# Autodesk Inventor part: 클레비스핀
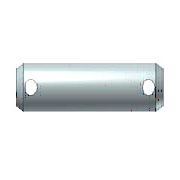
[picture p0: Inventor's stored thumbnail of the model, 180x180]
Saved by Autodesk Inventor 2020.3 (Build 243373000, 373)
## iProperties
Created: 2012-02
Part Number: 클레비스핀
Material: 강철
Description: 머리가 없는 클레비스 핀 B
Document SubType Name: Modeling
Standard: ISO 2340
Designer: mduedu
Standard Revision: Second edition 1986-11-01
Standards Organization: ISO
Language: ko-KR
Size Designation: B - 8 x 45
Categories: <MemberInstance><Categories><Category DisplayName="조임쇠" InternalName="e4da775c-781d-43d5-af7c-5136215cf5a6" Mnemonic="FSTN"><Category DisplayName="핀" InternalNa
Density: 7.85 g/cm^3
Appearance: 반광택
IsCustomPart: 1
Author: mduedu
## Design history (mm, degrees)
sketch "스케치1"
  geometry: L1 (-4.5, 0)-(-4.5, 4); L2 (-4.5, 4)-(35.5, 4); L3 (35.5, 4)-(35.5, 0); L4 (-4.5, 0)-(35.5, 0); L5 (0, -2)-(0, 5) reference; L6 (-13.5, 0)-(49.5, 0) reference; C1 r 1 at (-1, 0); C2 r 1 at (32, 0)
  constraints: 8 end point, 2 centre point, 2 perpendicular, 2 point on line, 1 collinear, 1 parallel, 1 tangent, 1 vertical
  dimensions: "d0" = 8 diameter of L2 L4 (= NND); "d1" = 40 distance of L1.end L2.end (= NLG); "d2" = 3.5 distance from line of L1 C1.centre (= DIST1); "d3" = 3.5 distance from line of L3 C2.centre (= DIST2); "d4" = 2 diameter of C1 (= BOR1); "d5" = 2 diameter of C2 (= BOR2)
revolve "본체" stored, may be unused: angle "d7" = 90 deg
extrude "구멍1" cut sketch "스케치1" extent not by distance; taper "d6" = 0 deg; stored distance "d8" = 10
extrude "구멍2" cut sketch "스케치1" extent not by distance; taper "d13" = 0 deg; stored distance "d14" = 10
workaxis "Work Axis1"
workaxis "Work Axis2"
workplane "Work Plane1"
node "작업 평면5"
body "Solid1"
chamfer "모따기2" distance "d9" = 2 (= PHH2); stored, may be unused: angle "d10" = 30 deg (= FAWI2), second distance "d40" = 2 (= PHH2)
chamfer "모따기1" distance "d11" = 2 (= PHH1); stored, may be unused: angle "d12" = 30 deg (= FAWI1), second distance "d41" = 2 (= PHH1)
other parameters: "NLG" = 40 [user parameter; used in 1 equation term], "NND" = 8 [user parameter; used in 1 equation term], "PHH1" = 2 [user parameter; used in 3 equation terms], "PHH2" = 2 (= PHH1) [user parameter; used in 2 equation terms], "FAWI1" = 30 deg [user parameter; used in 1 equation term], "FAWI2" = 30 deg [user parameter; used in 1 equation term], "DIST1" = 3.5 [user parameter; used in 4 equation terms], "DIST2" = 3.5 (= DIST1) [user parameter; used in 1 equation term], "BOR1" = 2 [user parameter; used in 4 equation terms], "BOR2" = 2 (= BOR1) [user parameter; used in 1 equation term], "d15" = 0, "d42" = 0, "d43" = 0, "d44" = -4.5 (= -0.5 x BOR1 - DIST1), "d45" = -4.5 (= -0.5 x BOR1 - DIST1), "d47" = 0, "d48" = 0, "d49" = 0, "d50" = 0, "d51" = 0, "d52" = 0
